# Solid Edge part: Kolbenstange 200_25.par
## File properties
Username: ahadarics
Dokumentum tartalom típus: 0
Author: ahadarics
Last saved by: ahadarics
Revision: 78
Sűrűség: 0,000 kg/m^3
Pontosság: 0,990
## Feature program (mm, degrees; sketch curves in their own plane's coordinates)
base feature "unnamed BaseFeature 1"
thread "unnamed Thread 1"
chamfer "Letörés_1"  SetBackValue2 = 20 deg
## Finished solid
Body 1: solid body, 19 faces, 27 edges, 11 vertices.
  Faces by surface: plane 8, cylinder 5, cone 3, torus 3
  Edges by curve: circle 15, line 7, curve on surface 3, ellipse 2
Bounding box of the edges (mm; curved faces can reach further): 200.000 x 200.000 x 322.000, from (-100, -100, -181) to (100, 100, 141).
Cylindrical faces by radius (mm): R16.4 x1, R18 x1, R19.5 x1, R20 x1, R100 x1
Conical faces (half-angle, radius in mm at the cone's reference point): 20 deg R18 x1, 30 deg R19.75 x1, 60 deg R17.2 x1
Toroidal faces (ring radius, tube radius in mm): R17.2 r0.8 x2, R17.7 r1.8 x1
Planar faces by outward normal: +x 1, +z 3, -x 1, -z 1, oblique 2
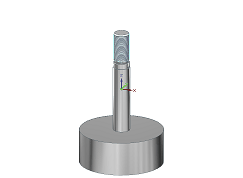
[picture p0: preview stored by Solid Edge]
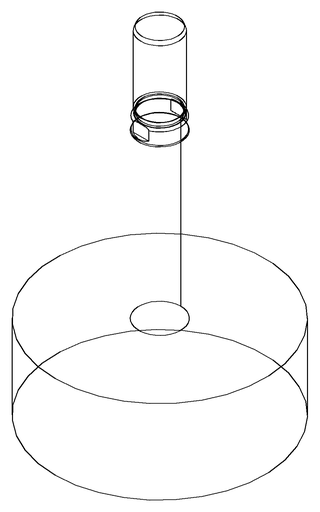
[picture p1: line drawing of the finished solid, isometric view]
